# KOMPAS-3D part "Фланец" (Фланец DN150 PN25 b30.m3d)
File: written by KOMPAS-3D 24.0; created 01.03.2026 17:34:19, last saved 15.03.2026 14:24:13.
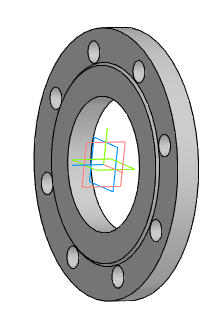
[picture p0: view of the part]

Document properties: Автор: R2D2; Полное имя файла: E:\Работа\Зайцев\GVWR2434M-2W-F-ОСТ Задвижка клиновая с выдвижным штоком DN.ru Ду50-300 Ру25\исходные материалы\DN150\Фланец DN150 PN25 b30.m3d

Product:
- Part/product: Фланец
    Масса: 10.899658
    additional columns: Типовые

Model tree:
1. Эскиз:2
2. Элемент вращения:1
     Угол 1 = 360
3. Эскиз:3  (with: Грань.Элемент вращения:1)
4. Элемент выдавливания:2
     Расстояние 2 = 27
5. Массив по концентрической сетке:1  (with: Элемент выдавливания:2, Эскиз:3, Грань.Элемент вращения:1)  (8 pattern instances)
     Шаг 2 = 360
6. Эскиз:4  (with: Грань.Элемент вращения:1)
7. Элемент выдавливания:3
     Расстояние 2 = 4

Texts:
  Линейный размер с обрывом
